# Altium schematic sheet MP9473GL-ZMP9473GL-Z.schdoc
size 127 x 101 mm
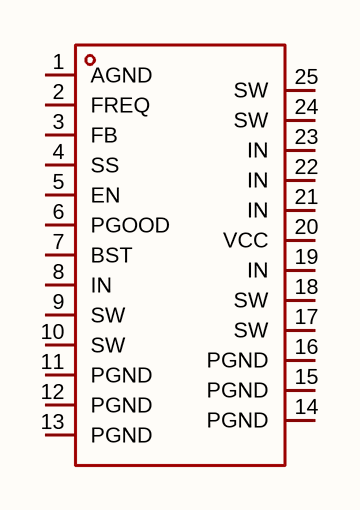
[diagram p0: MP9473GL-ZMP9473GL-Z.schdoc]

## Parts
U?  mp9473gl-z  [QFN-20_L4.0-W3.0-P0.5-MP9447GL-P]  (value not drawn)

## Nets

Not connected (* = marked no-connect by the designer): U? 1(AGND) 2(FREQ) 3(FB) 4(SS) 5(EN) 6(PGOOD) 7(BST) 8(IN) 9(SW) 10(SW) 11(PGND) 12(PGND) 13(PGND) 14(PGND) 15(PGND) 16(PGND) 17(SW) 18(SW) 19(IN) 20(VCC) 21(IN) 22(IN) 23(IN) 24(SW) 25(SW)

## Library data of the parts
U? = mp9473gl-z: 功能类型:降压型;工作电压:4.5V~36V;输出电压:800mV~32.4V;输出电流:3.5A;输出类型:可调;; Manufacturer: MPS(芯源); AddInBom: yes; Function: 降压型; Output Current: 3.5A; Frequency - Switching: 200kHz~1MHz; Synchronous Rectifier: 是; Number of Outputs: 1; Topology: 降压式; Quiescent Current: 500uA; Switch tube (built-in/external): 内置; Output Type: 可调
